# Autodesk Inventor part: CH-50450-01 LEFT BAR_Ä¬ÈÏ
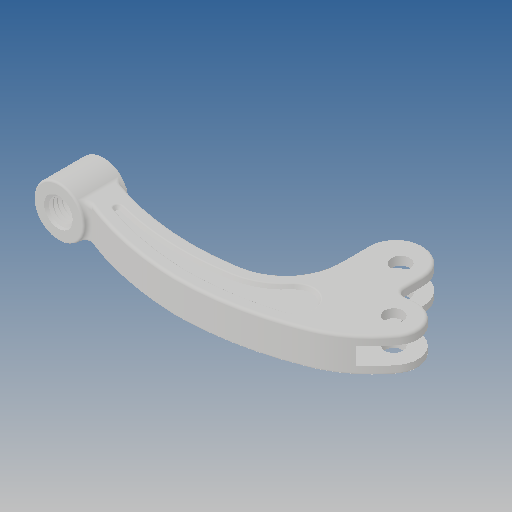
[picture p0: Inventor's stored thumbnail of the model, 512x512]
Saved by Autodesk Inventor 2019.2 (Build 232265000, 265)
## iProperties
Created: 2010-06
Part Number: CH-50450-01 LEFT BAR_Ä¬ÈÏ
Material: Ogólny
Document SubType Name: Modeling
Designer: CADENGINEERING4
Density: 1 g/cm^3
Appearance: Domyślna
Author: CADENGINEERING4
Revision Number: ÈÎºÎ
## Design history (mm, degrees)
feature "NONE"
node "Bryła1"
